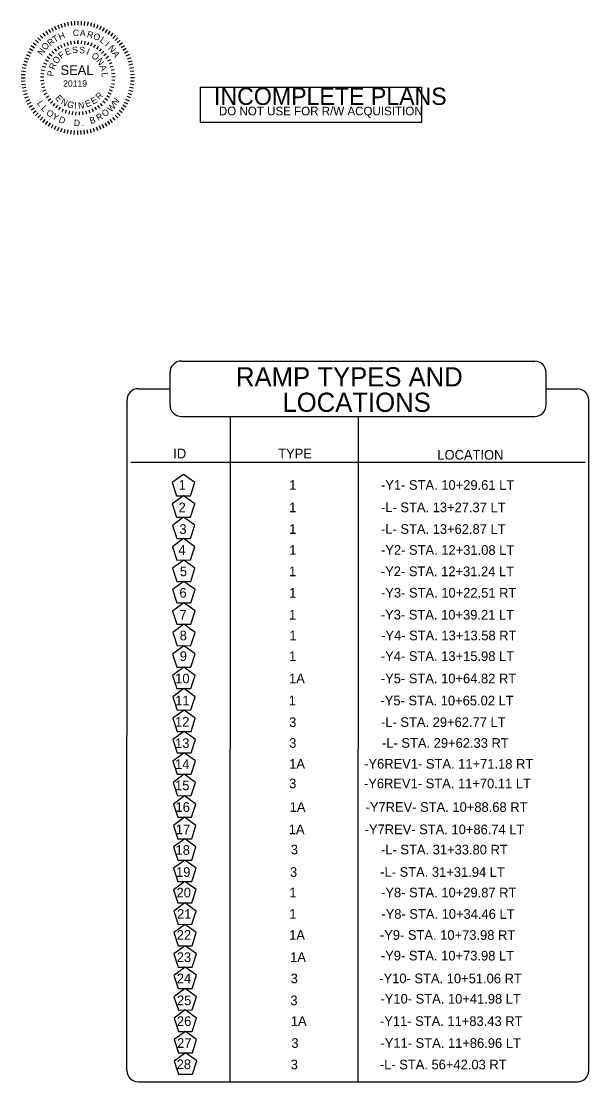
# Model space of a CAD drawing. Extents: x 1727387 to 1728895, y 539219 to 540208.
# Drawn here: x 1728485 to 1728895, y 539219 to 539985 of the extents above; entities that cross this region are included whole.
import ezdxf

# ---------------------------------------------------------------- set-up
doc = ezdxf.new("R2010")
doc.units = 0
for name, color, linetype in [('Default', 7, 'Continuous'), ('DEV BORDER CELL', 7, 'Continuous'), ('Gray Area Fill Shapes', 7, 'Continuous'), ('Sheet Sticker Incomplete CELL', 7, 'Continuous'), ('Sheet Title CELL', 7, 'Continuous')]:
    doc.layers.add(name, color=color, linetype=linetype)

msp = doc.modelspace()

# ---------------------------------------------------------------- linework, layer by layer
at = {"layer": 'Default'}
for p, q in [((1728636.06, 539699.31), (1728635.95, 539218.92)), ((1728728.48, 539699.31), (1728728.37, 539218.92)), ((1728564.36, 539666.22), (1728728.48, 539666.18)), ((1728728.48, 539666.18), (1728892.59, 539666.14))]:
    msp.add_line(p, q, dxfattribs=at)
for points in [[(1728602.33, 539657.43), (1728594.22, 539651.5), (1728597.36, 539641.96), (1728607.4, 539641.99), (1728610.48, 539651.55)], [(1728602.38, 539641.97), (1728594.27, 539636.04), (1728597.41, 539626.5), (1728607.46, 539626.53), (1728610.53, 539636.1)], [(1728602.43, 539626.52), (1728594.33, 539620.58), (1728597.46, 539611.04), (1728607.51, 539611.07), (1728610.58, 539620.64)], [(1728602.48, 539611.06), (1728594.38, 539605.13), (1728597.51, 539595.58), (1728607.56, 539595.62), (1728610.63, 539605.18)], [(1728602.54, 539595.6), (1728594.43, 539589.67), (1728597.57, 539580.13), (1728607.61, 539580.16), (1728610.68, 539589.72)], [(1728602.59, 539580.14), (1728594.48, 539574.21), (1728597.62, 539564.67), (1728607.66, 539564.7), (1728610.73, 539574.27)], [(1728602.64, 539564.68), (1728594.53, 539558.75), (1728597.67, 539549.21), (1728607.71, 539549.24), (1728610.79, 539558.81)], [(1728602.69, 539549.23), (1728594.58, 539543.3), (1728597.72, 539533.75), (1728607.77, 539533.79), (1728610.84, 539543.35)], [(1728602.61, 539533.68), (1728594.51, 539527.74), (1728597.64, 539518.2), (1728607.69, 539518.23), (1728610.76, 539527.8)], [(1728602.67, 539518.22), (1728594.56, 539512.29), (1728597.7, 539502.74), (1728607.74, 539502.78), (1728610.81, 539512.34)], [(1728602.72, 539502.76), (1728594.61, 539496.83), (1728597.75, 539487.29), (1728607.79, 539487.32), (1728610.86, 539496.88)], [(1728602.77, 539487.3), (1728594.66, 539481.37), (1728597.8, 539471.83), (1728607.84, 539471.86), (1728610.92, 539481.43)], [(1728602.82, 539471.84), (1728594.71, 539465.91), (1728597.85, 539456.37), (1728607.9, 539456.4), (1728610.97, 539465.97)], [(1728602.87, 539456.39), (1728594.77, 539450.46), (1728597.9, 539440.91), (1728607.95, 539440.95), (1728611.02, 539450.51)], [(1728602.93, 539440.93), (1728594.82, 539435), (1728597.95, 539425.45), (1728608, 539425.49), (1728611.07, 539435.05)], [(1728603.17, 539425.33), (1728595.07, 539419.4), (1728598.2, 539409.86), (1728608.25, 539409.89), (1728611.32, 539419.45)], [(1728603.22, 539409.87), (1728595.12, 539403.94), (1728598.25, 539394.4), (1728608.3, 539394.43), (1728611.37, 539404)], [(1728603.28, 539394.41), (1728595.17, 539388.48), (1728598.31, 539378.94), (1728608.35, 539378.97), (1728611.42, 539388.54)], [(1728603.33, 539378.96), (1728595.22, 539373.03), (1728598.36, 539363.48), (1728608.4, 539363.52), (1728611.47, 539373.08)], [(1728603.38, 539363.5), (1728595.27, 539357.57), (1728598.41, 539348.02), (1728608.45, 539348.06), (1728611.53, 539357.62)], [(1728603.43, 539348.04), (1728595.32, 539342.11), (1728598.46, 539332.57), (1728608.51, 539332.6), (1728611.58, 539342.16)], [(1728603.48, 539332.58), (1728595.38, 539326.65), (1728598.51, 539317.11), (1728608.56, 539317.14), (1728611.63, 539326.71)], [(1728603.53, 539317.13), (1728595.43, 539311.19), (1728598.56, 539301.65), (1728608.61, 539301.69), (1728611.68, 539311.25)], [(1728603.59, 539301.67), (1728595.48, 539295.74), (1728598.62, 539286.19), (1728608.66, 539286.23), (1728611.73, 539295.79)], [(1728603.64, 539286.21), (1728595.53, 539280.28), (1728598.67, 539270.74), (1728608.71, 539270.77), (1728611.78, 539280.33)], [(1728603.69, 539270.75), (1728595.58, 539264.82), (1728598.72, 539255.28), (1728608.76, 539255.31), (1728611.84, 539264.88)], [(1728603.74, 539255.3), (1728595.63, 539249.36), (1728598.77, 539239.82), (1728608.82, 539239.85), (1728611.89, 539249.42)], [(1728603.79, 539239.84), (1728595.69, 539233.91), (1728598.82, 539224.36), (1728608.87, 539224.4), (1728611.94, 539233.96)]]:
    msp.add_lwpolyline(points, close=True, dxfattribs=at)
at = {"layer": 'DEV BORDER CELL'}
for p, q in [((1728521.13, 539984.28), (1728521.46, 539981.51)), ((1728523.59, 539984.5), (1728523.76, 539981.72)), ((1728526.06, 539984.57), (1728526.06, 539981.78)), ((1728528.53, 539984.49), (1728528.36, 539981.71)), ((1728530.99, 539984.27), (1728530.65, 539981.5)), ((1728502.83, 539977.36), (1728504.41, 539975.06)), ((1728504.91, 539978.7), (1728506.35, 539976.31)), ((1728507.06, 539979.91), (1728508.35, 539977.44)), ((1728509.28, 539980.98), (1728510.42, 539978.44)), ((1728511.56, 539981.93), (1728512.55, 539979.32)), ((1728513.9, 539982.73), (1728514.72, 539980.07)), ((1728516.28, 539983.39), (1728516.94, 539980.69)), ((1728518.69, 539983.91), (1728519.19, 539981.17)), ((1728533.43, 539983.9), (1728532.92, 539981.16)), ((1728535.84, 539983.38), (1728535.17, 539980.67)), ((1728538.22, 539982.71), (1728537.39, 539980.05)), ((1728540.55, 539981.9), (1728539.56, 539979.3)), ((1728542.83, 539980.95), (1728541.69, 539978.41)), ((1728545.05, 539979.87), (1728543.75, 539977.4)), ((1728547.2, 539978.66), (1728545.76, 539976.27)), ((1728549.27, 539977.31), (1728547.69, 539975.02)), ((1728493.87, 539968.93), (1728496.06, 539967.21)), ((1728495.45, 539970.83), (1728497.54, 539968.98)), ((1728497.15, 539972.62), (1728499.11, 539970.65)), ((1728498.95, 539974.31), (1728500.79, 539972.23)), ((1728500.85, 539975.9), (1728502.56, 539973.7)), ((1728515.89, 539968.66), (1728516.76, 539966.5)), ((1728518.34, 539969.52), (1728519, 539967.29)), ((1728520.87, 539970.14), (1728521.31, 539967.86)), ((1728523.45, 539970.51), (1728523.67, 539968.2)), ((1728526.05, 539970.63), (1728526.05, 539968.31)), ((1728526.05, 539968.31), (1728526.05, 539970.63)), ((1728528.65, 539970.51), (1728528.42, 539968.2)), ((1728531.22, 539970.13), (1728530.78, 539967.85)), ((1728533.75, 539969.5), (1728533.08, 539967.28)), ((1728551.26, 539975.85), (1728549.54, 539973.66)), ((1728553.16, 539974.26), (1728551.31, 539972.18)), ((1728554.95, 539972.57), (1728552.98, 539970.6)), ((1728556.64, 539970.77), (1728554.56, 539968.93)), ((1728558.22, 539968.87), (1728556.03, 539967.16)), ((1728489.85, 539962.72), (1728492.31, 539961.43)), ((1728491.06, 539964.88), (1728493.44, 539963.43)), ((1728492.4, 539966.95), (1728494.69, 539965.36)), ((1728505.45, 539961.09), (1728507.22, 539959.59)), ((1728507.22, 539962.99), (1728508.85, 539961.33)), ((1728509.17, 539964.72), (1728510.63, 539962.9)), ((1728511.28, 539966.24), (1728512.55, 539964.3)), ((1728513.53, 539967.56), (1728514.6, 539965.5)), ((1728536.21, 539968.64), (1728535.33, 539966.49)), ((1728538.56, 539967.54), (1728537.49, 539965.48)), ((1728540.81, 539966.22), (1728539.53, 539964.27)), ((1728542.91, 539964.68), (1728541.46, 539962.87)), ((1728544.86, 539962.96), (1728543.23, 539961.29)), ((1728546.63, 539961.05), (1728544.85, 539959.55)), ((1728559.68, 539966.88), (1728557.39, 539965.3)), ((1728561.02, 539964.81), (1728558.64, 539963.37)), ((1728562.24, 539962.66), (1728559.76, 539961.36)), ((1728486.34, 539953.51), (1728489.05, 539952.85)), ((1728487.01, 539955.89), (1728489.67, 539955.06)), ((1728487.81, 539958.22), (1728490.42, 539957.23)), ((1728488.77, 539960.5), (1728491.3, 539959.36)), ((1728501.33, 539954.48), (1728503.46, 539953.55)), ((1728502.49, 539956.81), (1728504.52, 539955.68)), ((1728503.86, 539959.02), (1728505.77, 539957.7)), ((1728548.21, 539958.98), (1728546.3, 539957.66)), ((1728549.58, 539956.77), (1728547.55, 539955.64)), ((1728550.73, 539954.43), (1728548.6, 539953.51)), ((1728563.31, 539960.43), (1728560.77, 539959.3)), ((1728564.26, 539958.15), (1728561.65, 539957.17)), ((1728565.06, 539955.82), (1728562.4, 539955)), ((1728565.72, 539953.44), (1728563.01, 539952.78)), ((1728485.22, 539946.2), (1728488, 539946.03)), ((1728485.45, 539948.66), (1728488.21, 539948.32)), ((1728485.82, 539951.1), (1728488.56, 539950.6)), ((1728499.28, 539946.97), (1728501.58, 539946.69)), ((1728499.72, 539949.53), (1728501.99, 539949.03)), ((1728500.41, 539952.04), (1728502.62, 539951.33)), ((1728551.65, 539951.99), (1728549.44, 539951.28)), ((1728552.33, 539949.48), (1728550.07, 539948.99)), ((1728552.77, 539946.92), (1728550.47, 539946.64)), ((1728566.24, 539951.03), (1728563.5, 539950.53)), ((1728566.6, 539948.58), (1728563.84, 539948.25)), ((1728566.83, 539946.13), (1728564.04, 539945.96)), ((1728485.15, 539943.73), (1728487.93, 539943.73)), ((1728485.22, 539941.26), (1728488, 539941.43)), ((1728485.44, 539938.81), (1728488.21, 539939.14)), ((1728499.09, 539944.37), (1728501.41, 539944.31)), ((1728499.15, 539941.77), (1728501.46, 539941.93)), ((1728499.47, 539939.18), (1728501.75, 539939.57)), ((1728550.3, 539939.61), (1728552.59, 539939.22)), ((1728552.89, 539941.72), (1728550.58, 539941.89)), ((1728552.96, 539944.32), (1728550.64, 539944.27)), ((1728566.59, 539938.73), (1728563.83, 539939.07)), ((1728566.82, 539941.19), (1728564.04, 539941.36)), ((1728566.9, 539943.66), (1728564.11, 539943.66)), ((1728485.81, 539936.36), (1728488.55, 539936.86)), ((1728486.32, 539933.95), (1728489.03, 539934.61)), ((1728486.98, 539931.57), (1728489.65, 539932.39)), ((1728500.02, 539936.64), (1728502.26, 539937.25)), ((1728500.82, 539934.16), (1728503, 539934.98)), ((1728501.86, 539931.78), (1728503.94, 539932.81)), ((1728503.12, 539929.5), (1728505.1, 539930.72)), ((1728548.9, 539929.46), (1728546.92, 539930.68)), ((1728550.16, 539931.73), (1728548.08, 539932.77)), ((1728551.2, 539934.12), (1728549.03, 539934.94)), ((1728552.01, 539936.59), (1728549.77, 539937.2)), ((1728565.04, 539931.5), (1728562.37, 539932.33)), ((1728565.7, 539933.88), (1728563, 539934.54)), ((1728566.22, 539936.29), (1728563.48, 539936.79)), ((1728487.79, 539929.24), (1728490.4, 539930.22)), ((1728488.74, 539926.96), (1728491.28, 539928.09)), ((1728489.81, 539924.73), (1728492.28, 539926.03)), ((1728491.02, 539922.58), (1728493.41, 539924.02)), ((1728504.6, 539927.36), (1728506.45, 539928.76)), ((1728506.28, 539925.37), (1728507.98, 539926.94)), ((1728508.14, 539923.55), (1728509.68, 539925.28)), ((1728510.17, 539921.92), (1728511.53, 539923.79)), ((1728541.84, 539921.89), (1728540.48, 539923.77)), ((1728543.87, 539923.51), (1728542.33, 539925.25)), ((1728545.73, 539925.33), (1728544.04, 539926.91)), ((1728547.41, 539927.32), (1728545.57, 539928.73)), ((1728560.98, 539922.51), (1728558.6, 539923.96)), ((1728562.2, 539924.67), (1728559.73, 539925.96)), ((1728563.28, 539926.89), (1728560.74, 539928.03)), ((1728564.23, 539929.17), (1728561.62, 539930.16)), ((1728492.36, 539920.51), (1728494.65, 539922.09)), ((1728493.82, 539918.52), (1728496.02, 539920.23)), ((1728495.4, 539916.62), (1728497.49, 539918.46)), ((1728497.09, 539914.82), (1728499.06, 539916.79)), ((1728498.89, 539913.13), (1728500.74, 539915.21)), ((1728512.34, 539920.49), (1728513.52, 539922.49)), ((1728514.65, 539919.28), (1728515.63, 539921.38)), ((1728517.06, 539918.29), (1728517.83, 539920.48)), ((1728520.09, 539919.8), (1728519.53, 539917.54)), ((1728522.11, 539917.04), (1728522.44, 539919.34)), ((1728524.7, 539916.79), (1728524.81, 539919.11)), ((1728527.3, 539916.78), (1728527.19, 539919.1)), ((1728529.89, 539917.03), (1728529.56, 539919.33)), ((1728532.45, 539917.53), (1728531.89, 539919.79)), ((1728534.94, 539918.27), (1728534.17, 539920.47)), ((1728537.35, 539919.26), (1728536.37, 539921.36)), ((1728539.66, 539920.46), (1728538.48, 539922.47)), ((1728553.1, 539913.08), (1728551.25, 539915.16)), ((1728554.9, 539914.77), (1728552.93, 539916.74)), ((1728556.59, 539916.56), (1728554.51, 539918.41)), ((1728558.18, 539918.46), (1728555.99, 539920.18)), ((1728559.64, 539920.44), (1728557.35, 539922.03)), ((1728500.79, 539911.54), (1728502.5, 539913.73)), ((1728502.77, 539910.08), (1728504.36, 539912.37)), ((1728504.84, 539908.73), (1728506.29, 539911.12)), ((1728506.99, 539907.52), (1728508.29, 539909.99)), ((1728509.21, 539906.44), (1728510.36, 539908.98)), ((1728511.49, 539905.49), (1728512.49, 539908.09)), ((1728540.48, 539905.46), (1728539.49, 539908.07)), ((1728542.76, 539906.41), (1728541.62, 539908.95)), ((1728544.98, 539907.48), (1728543.69, 539909.95)), ((1728547.14, 539908.7), (1728545.7, 539911.08)), ((1728549.21, 539910.03), (1728547.63, 539912.33)), ((1728551.2, 539911.49), (1728549.49, 539913.69)), ((1728513.82, 539904.68), (1728514.66, 539907.34)), ((1728516.21, 539904.02), (1728516.87, 539906.72)), ((1728518.62, 539903.49), (1728519.12, 539906.23)), ((1728521.06, 539903.12), (1728521.39, 539905.89)), ((1728523.52, 539902.9), (1728523.69, 539905.68)), ((1728525.98, 539902.82), (1728525.99, 539905.61)), ((1728528.45, 539902.89), (1728528.29, 539905.67)), ((1728530.91, 539903.12), (1728530.58, 539905.88)), ((1728533.35, 539903.48), (1728532.85, 539906.22)), ((1728535.77, 539904), (1728535.11, 539906.7)), ((1728538.15, 539904.66), (1728537.32, 539907.32))]:
    msp.add_line(p, q, dxfattribs=at)
at = {"layer": 'Sheet Sticker Incomplete CELL'}
msp.add_lwpolyline([(1728614.73, 539911.45), (1728614.73, 539936.95), (1728774.22, 539936.95), (1728774.22, 539911.45)], close=True, dxfattribs=at)
at = {"layer": 'Sheet Title CELL'}
for p, q in [((1728600.85, 539739.22), (1728856.12, 539739.08)), ((1728592.67, 539707.49), (1728592.67, 539731.04)), ((1728864.3, 539707.49), (1728864.3, 539730.9)), ((1728569.77, 539719.26), (1728592.67, 539719.26)), ((1728864.3, 539719.2), (1728887.01, 539719.2)), ((1728561.55, 539227.1), (1728561.59, 539711.09)), ((1728895.14, 539227.1), (1728895.19, 539711.02)), ((1728600.85, 539699.31), (1728856.12, 539699.31)), ((1728569.73, 539218.92), (1728886.96, 539218.92))]:
    msp.add_line(p, q, dxfattribs=at)
for centre, start, end in [((1728600.85, 539731.04), 90, 180), ((1728856.12, 539730.9), 360, 90), ((1728569.77, 539711.09), 90, 180), ((1728887.01, 539711.02), 360, 90), ((1728600.85, 539707.49), 180, 270), ((1728856.12, 539707.49), 270, 360), ((1728569.73, 539227.1), 180, 270), ((1728886.96, 539227.1), 270, 360)]:
    msp.add_arc(centre, 8.18, start, end, dxfattribs=at)

# ---------------------------------------------------------------- texts
at = {"layer": 'Default'}
for s, height, p in [('ID', 6.978, (1728595.01, 539668.98)), ('TYPE', 6.978, (1728670.8, 539668.97)), ('LOCATION', 6.978, (1728785.79, 539668.06)), ('1', 6.98, (1728598.85, 539646.27)), ('1', 6.98, (1728678.74, 539646.27)), ('-Y1- STA. 10+29.61 LT', 6.9784, (1728745.07, 539646.32)), ('2', 6.98, (1728598.85, 539630.1)), ('1', 6.98, (1728678.74, 539630.11)), ('-L- STA. 13+27.37 LT', 6.9784, (1728745.07, 539630.15)), ('3', 6.98, (1728599.43, 539614.46)), ('1', 6.98, (1728678.74, 539614.47)), ('-L- STA. 13+62.87 LT', 6.9784, (1728745.07, 539614.51)), ('4', 6.98, (1728598.71, 539599.34)), ('1', 6.98, (1728678.76, 539599.35)), ('-Y2- STA. 12+31.08 LT', 6.9784, (1728745.09, 539599.39)), ('5', 6.98, (1728599.75, 539583.93)), ('1', 6.98, (1728678.63, 539583.93)), ('-Y2- STA. 12+31.24 LT', 6.9784, (1728744.97, 539583.97)), ('6', 6.98, (1728599.47, 539568.47)), ('1', 6.98, (1728678.74, 539568.48)), ('-Y3- STA. 10+22.51 RT', 6.9784, (1728745.07, 539568.52)), ('7', 6.98, (1728599.49, 539552.61)), ('1', 6.98, (1728678.61, 539552.62)), ('-Y3- STA. 10+39.21 LT', 6.9784, (1728744.94, 539552.66)), ('8', 6.98, (1728599.62, 539537.62)), ('1', 6.98, (1728678.82, 539537.62)), ('-Y4- STA. 13+13.58 RT', 6.9784, (1728745.15, 539537.66)), ('9', 6.98, (1728599.68, 539522.73)), ('1', 6.98, (1728678.66, 539522.74)), ('-Y4- STA. 13+15.98 LT', 6.9784, (1728745, 539522.78)), ('10', 6.978, (1728596.41, 539506.61)), ('1A', 6.978, (1728678.61, 539506.61)), ('-Y5- STA. 10+64.82 RT', 6.9784, (1728744.94, 539506.66)), ('11', 6.978, (1728596.34, 539490.65)), ('1', 6.98, (1728678.34, 539490.65)), ('-Y5- STA. 10+65.02 LT', 6.9784, (1728744.68, 539490.69)), ('12', 6.978, (1728596.29, 539475.37)), ('3', 6.98, (1728678.74, 539475.06)), ('-L- STA. 29+62.77 LT', 6.9784, (1728745.07, 539475.11)), ('13', 6.978, (1728596.28, 539459.9)), ('3', 6.98, (1728678.74, 539460.04)), ('-L- STA. 29+62.33 RT', 6.9784, (1728745.8, 539460.09)), ('14', 6.978, (1728596.28, 539444.73)), ('1A', 6.978, (1728678.74, 539445.01)), ('-Y6REV1- STA. 11+71.18 RT', 6.9784, (1728732.89, 539445.06)), ('15', 6.978, (1728596.3, 539429.41)), ('3', 6.98, (1728678.74, 539430.81)), ('-Y6REV1- STA. 11+70.11 LT', 6.9784, (1728732.74, 539430.86)), ('16', 6.978, (1728596.63, 539413.78)), ('1A', 6.978, (1728679.1, 539413.78)), ('-Y7REV- STA. 10+88.68 RT', 6.9784, (1728733.93, 539413.83)), ('17', 6.978, (1728596.89, 539397.66)), ('1A', 6.978, (1728678.44, 539397.66)), ('-Y7REV- STA. 10+86.74 LT', 6.9784, (1728733.24, 539397.7)), ('18', 6.978, (1728596.66, 539382.78)), ('3', 6.98, (1728679.89, 539383.07)), ('-L- STA. 31+33.80 RT', 6.9784, (1728745.07, 539383.11)), ('19', 6.978, (1728596.99, 539366.87)), ('3', 6.98, (1728679.32, 539366.87)), ('-L- STA. 31+31.94 LT', 6.9784, (1728744.52, 539366.92)), ('20', 6.978, (1728597.37, 539352.06)), ('1', 6.98, (1728678.79, 539352.06)), ('-Y8- STA. 10+29.87 RT', 6.9784, (1728745.12, 539352.11)), ('21', 6.978, (1728597.72, 539336.58)), ('1', 6.98, (1728678.79, 539336.58)), ('-Y8- STA. 10+34.46 LT', 6.9784, (1728745.31, 539336.62)), ('22', 6.978, (1728597.47, 539321.41)), ('1A', 6.978, (1728678.72, 539321.41)), ('-Y9- STA. 10+73.98 RT', 6.9784, (1728744.28, 539321.45)), ('23', 6.978, (1728597.54, 539305.41)), ('1A', 6.978, (1728679.41, 539305.41)), ('-Y9- STA. 10+73.98 LT', 6.9784, (1728744.97, 539306.55)), ('24', 6.978, (1728597.53, 539290.05)), ('3', 6.98, (1728679.8, 539290.05)), ('-Y10- STA. 10+51.06 RT', 6.9784, (1728743.82, 539290.1)), ('25', 6.978, (1728597.66, 539274.2)), ('3', 6.98, (1728679.57, 539274.2)), ('-Y10- STA. 10+41.98 LT', 6.9784, (1728744.68, 539275.4)), ('26', 6.978, (1728597.66, 539259.24)), ('1A', 6.978, (1728679.92, 539259.24)), ('-Y11- STA. 11+83.43 RT', 6.9784, (1728744.31, 539259.28)), ('27', 6.978, (1728597.78, 539243.41)), ('3', 6.98, (1728680.31, 539243.4)), ('-Y11- STA. 11+86.96 LT', 6.9784, (1728744.69, 539243.45)), ('28', 6.978, (1728597.45, 539228.06)), ('3', 6.98, (1728679.87, 539227.9)), ('-L- STA. 56+42.03 RT', 6.9784, (1728744.25, 539227.94))]:
    msp.add_text(s, height=height, rotation=359.94622, dxfattribs=at).set_placement(p)
at = {"layer": 'DEV BORDER CELL'}
for s, height, rotation, p in [('H', 4.64, 21.01464, (1728513.1, 539970.96)), ('C', 4.64, 357.30395, (1728522.34, 539973.94)), ('A', 4.64, 357.30395, (1728527.41, 539973.84)), ('R', 4.64, 345.29464, (1728532.32, 539973.15)), ('O', 4.64, 51.66428, (1728502.88, 539963.23)), ('R', 4.64, 38.60755, (1728506.24, 539966.35)), ('T', 4.64, 30.44658, (1728509.36, 539968.95)), ('O', 4.64, 342.23783, (1728536.82, 539971.81)), ('L', 4.64, 329.10154, (1728541.54, 539969.74)), ('I', 4.64, 319.52607, (1728545.28, 539967.04)), ('N', 4.64, 53.62371, (1728500.21, 539959.31)), ('F', 4.64, 38.1876, (1728514.14, 539957.13)), ('E', 4.64, 22.89135, (1728517.85, 539959.75)), ('S', 4.64, 7.5951, (1728522.21, 539961.34)), ('S', 4.64, 352.29886, (1728526.85, 539961.72)), ('I', 4.64, 337.00261, (1728531.78, 539960.72)), ('O', 4.64, 321.70637, (1728535.52, 539958.91)), ('N', 4.64, 310.23161, (1728547.6, 539964.85)), ('A', 4.64, 300.46408, (1728550.66, 539961.42)), ('R', 4.64, 68.78009, (1728509.21, 539949.23)), ('O', 4.64, 53.48384, (1728511.05, 539953.39)), ('N', 4.64, 306.41012, (1728539.09, 539955.79)), ('P', 4.64, 84.07634, (1728508.5, 539944.63)), ('SEAL', 6.965, 359.94698, (1728513.55, 539945.8)), ('A', 4.64, 291.11388, (1728541.63, 539951.99)), ('L', 4.64, 275.81763, (1728543.13, 539947.4)), ('20119', 4.64, 359.94698, (1728515.44, 539937.26)), ('E', 4.64, 310.01707, (1728509.38, 539928.97)), ('R', 4.64, 44.51187, (1728541.55, 539927.51)), ('L', 4.64, 303.882, (1728496.33, 539925.35)), ('L', 4.64, 311.95381, (1728499.2, 539921.36)), ('N', 4.64, 330.87215, (1728513.27, 539925.1)), ('G', 4.64, 339.63838, (1728517.81, 539922.92)), ('I', 4.64, 357.73318, (1728523.34, 539921.43)), ('N', 4.64, 5.36284, (1728526.49, 539921.27)), ('E', 4.64, 20.7549, (1728532.36, 539922.3)), ('E', 4.64, 30.74079, (1728537.13, 539924.28)), ('W', 4.64, 43.27141, (1728549.87, 539918.64)), ('N', 4.64, 52.15404, (1728553.77, 539923.31)), ('O', 4.64, 320.59656, (1728502.72, 539917.7)), ('Y', 4.64, 329.26915, (1728506.94, 539914.47)), ('D', 4.64, 338.24163, (1728511.77, 539911.83)), ('B', 4.64, 16.5636, (1728535.33, 539910.29)), ('R', 4.64, 25.56616, (1728540.69, 539912.4)), ('O', 4.64, 34.38878, (1728545.3, 539915.16)), ('D', 4.64, 356.03694, (1728523.05, 539909)), ('.', 4.64, 3.77928, (1728528.9, 539908.96))]:
    msp.add_text(s, height=height, rotation=rotation, dxfattribs=at).set_placement(p)
at = {"layer": 'Gray Area Fill Shapes'}
for s, height, p in [('RAMP TYPES AND', 13.8661, (1728640.31, 539720.89)), ('LOCATIONS', 13.866, (1728673.88, 539702.56))]:
    msp.add_text(s, height=height, rotation=360, dxfattribs=at).set_placement(p)
at = {"layer": 'Sheet Sticker Incomplete CELL'}
for s, height, p in [('INCOMPLETE PLANS', 12.499, (1728624.44, 539924.14)), ('DO NOT USE FOR R/W ACQUISITION', 6.2495, (1728627.96, 539916.6))]:
    msp.add_text(s, height=height, dxfattribs=at).set_placement(p)

doc.saveas('drawing.dxf')
